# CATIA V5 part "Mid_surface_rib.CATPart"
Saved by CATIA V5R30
Part number: Part1
Bounding box of the stored display mesh (mm): x -50 to 50, y -7.836 to 79.398, z 0 to 79.208
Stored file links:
  D:\PROJECTS\CATIA V56R 2020\Resources\Parts File\c17_catia_v6_6r2020_prt\Mid_surface_rib.CATPart
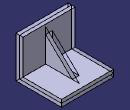
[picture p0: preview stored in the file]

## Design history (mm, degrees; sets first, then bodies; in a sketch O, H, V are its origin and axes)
Body1 (main body)
  Sketch1 on yz-plane, origin (0, 0, 0), H (0, 1, 0), V (0, 0, 1)
    line L1 (5.5044, 79.2082) -> (-7.8364, 79.2082)
    line L2 (-7.8364, 79.2082) -> (-7.8364, 0)
    point P3 (-7.8364, 0)
    line L3 (-7.8364, 0) -> (79.3978, 0)
    line L4 (79.3978, 0) -> (79.3978, 12.9983)
    line L5 (79.3978, 12.9983) -> (5.5044, 12.9983)
    line L6 (5.5044, 12.9983) -> (5.5044, 79.2082)
    horizontal: L1 H, L5 H, L3 H
    coincidence: P3 H
    vertical: L4 V, L6 V, L2 V
    parallelism: L5 L3
  Pad1: profile Sketch1, direction (-1, 0, 0), length 50, mirrored extent
  Sketch2 on yz-plane, origin (0, 0, 0), H (0, 1, 0), V (0, 0, 1)
    line L1 (56.7612, 12.9983) -> (5.5044, 61.9732)
    point P1 (56.7612, 12.9983)
    point P2 (5.5044, 61.9732)
    reference projected line E1 (5.5044, 18.7088) -> (5.5044, 69.2026) from edge [face of Pad1 from Sketch1.L6 | start face of Pad1]
    reference projected line E2 (79.0467, 12.9983) -> (8.5173, 12.9983) from edge [face of Pad1 from Sketch1.L5 | start face of Pad1]
    coincidence: P2 E1, P1 E2
  Stiffener1: ExtendedProfile Sketch2, ThicknessTop 0, ThicknessValue 13
  MidSurface1: InputSolid Stiffener1, FacePairs ({midsurfacefacepair Face1 face of Pad1 from Sketch1.L6, Face2 face of Pad1 from Sketch1.L2}; {midsurfacefacepair Face1 face of Pad1 from Sketch1.L5, Face2 face of Pad1 from Sketch1.L3}), OffsetRatio 0.5
  MidSurface2: InputSolid Stiffener1, FacePairs {midsurfacefacepair Face1 face of Stiffener1, Face2 face of Stiffener1}, OffsetRatio 0.5, LimitingMidSurface MidSurface1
